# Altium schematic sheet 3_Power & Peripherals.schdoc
size 309 x 223 mm; Symbol: Artery_A4; Device: Artery_A4; Company: Artery Technology; Drawed: SD; Version: 1.0; Page Size: A4; @Project Name: AT-START-F456; @Page Count: 4; @Update Date: 2025-01-22; @Create Date: 2024-11-08; @Schematic Name: AT-START-F456 V1.0; @Page No: 3; @Page Name: Power & Peripherals; @Board Name: AT-START-F456_V1.0; @Create Time: 17:57:27; @Update Time: 17:53:06
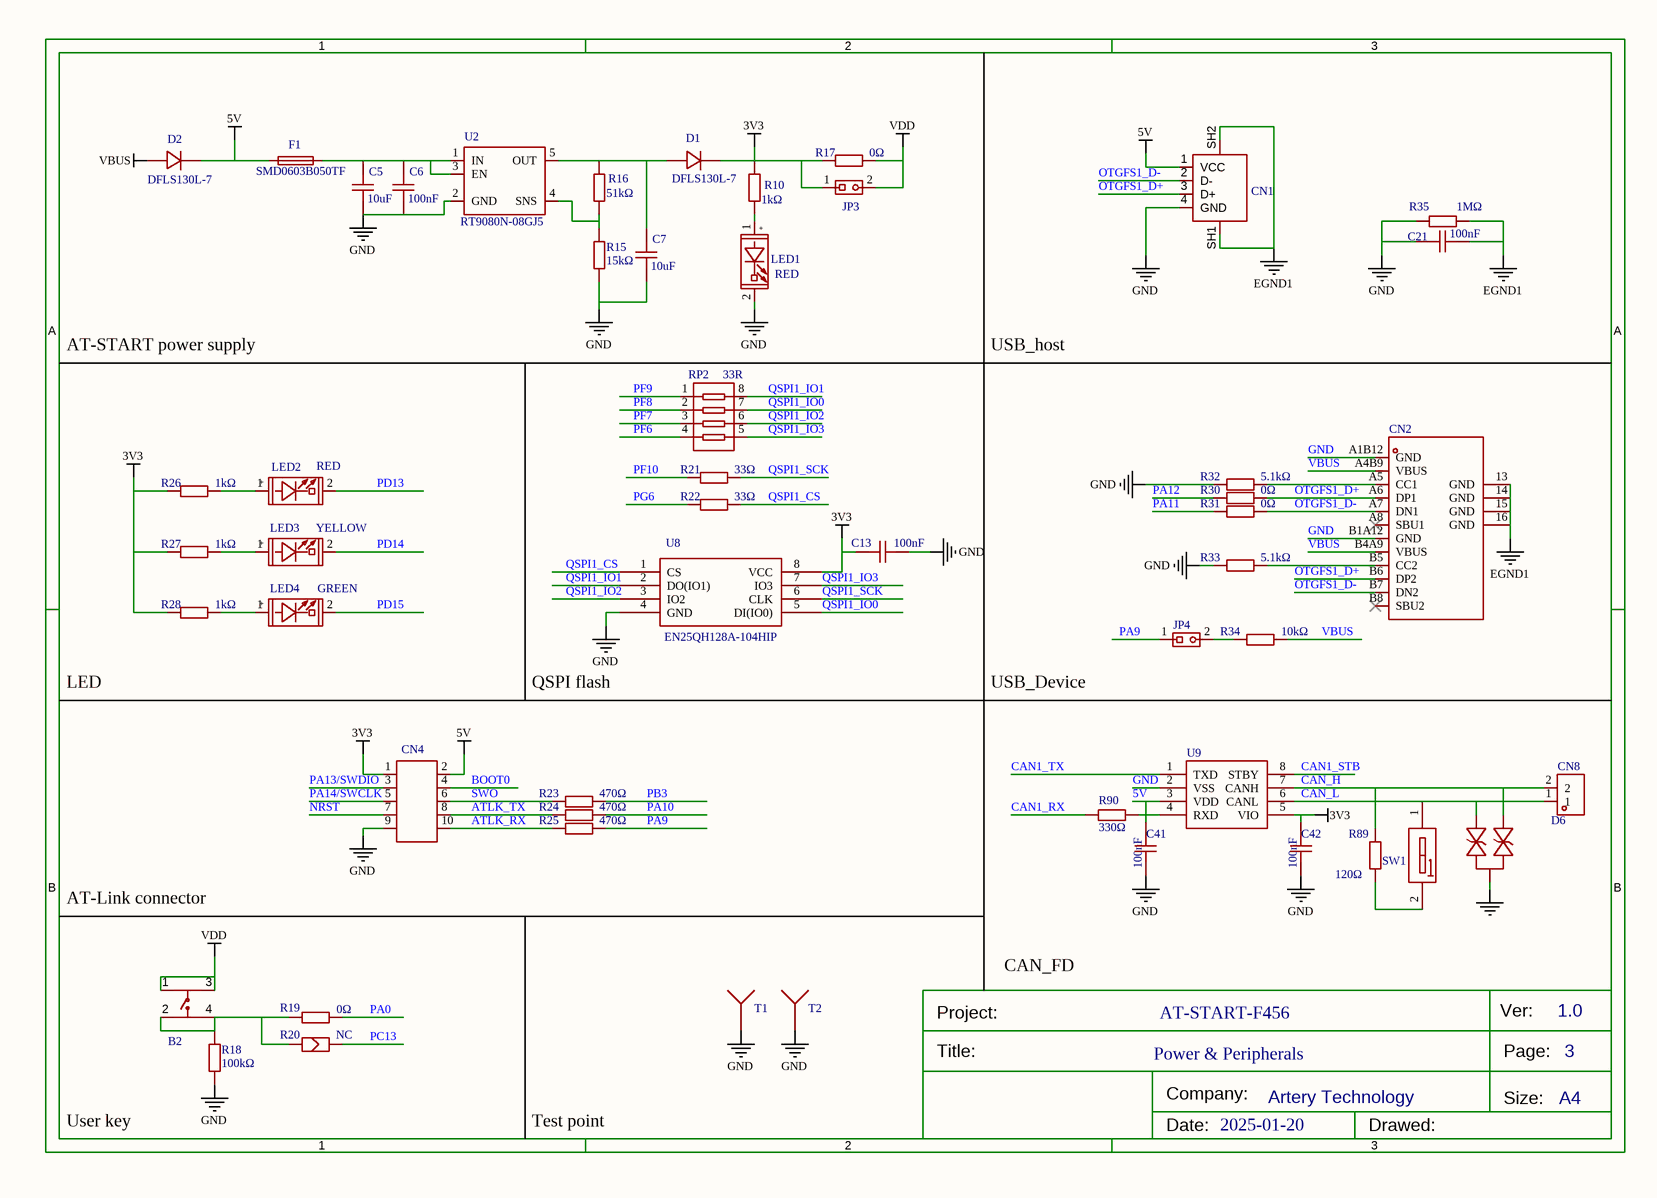
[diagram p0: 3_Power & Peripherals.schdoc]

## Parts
B2  贴片按键6*6*5 红色  [SW-SMD_4P-L6.0-W6.0-P4.50-LS9.0]  (value not drawn)
C5  10uF  [C0603]
C6  100nF  [C0603]
C7  10uF  [C0603]
C13  100nF  [C0603]
C21  100nF  [C0603]
C41  100nF  [C0603]
C42  100nF  [C0603]
CN1  JTJ-USB-AF-08  [USB-A-TH__USB-AF-90]  (value not drawn)
CN2  (no value)  [USB-C-SMD_TYPEC-304-BCP16]
CN4  CON10A_0  [HDR2X5]  (value not drawn)
CN8  KF301-5.0-2P  [CONN-TH_P5.00_KF301-5.0-2P]  (value not drawn)
D1  DFLS130L-7  [POWERDI-123_L2.8-W1.8-LS3.7-RD]
D2  DFLS130L-7  [POWERDI-123_L2.8-W1.8-LS3.7-RD]
D6  PESD2CANFD24V-TR  [SOT-23-3_L2.9-W1.3-P1.90-LS2.4-BR]  (value not drawn)
F1  SMD0603B050TF  [R0603]
JP3  Jumper 1x2P  [HEADER 1X2]  (value not drawn)
JP4  Jumper 1x2P  [HEADER 1X2]  (value not drawn)
LED1  RED  [LED0603]
LED2  RED  [LED0603]
LED3  YELLOW  [LED0603]
LED4  GREEN  [LED0603]
R10  1kΩ  [R0603]
R15  15kΩ  [R0603]
R16  51kΩ  [R0603]
R17  0Ω  [R0603]
R18  100kΩ  [R0603]
R19  0Ω  [R0603]
R20  NC  [SB-PAD]
R21  33Ω  [R0603]
R22  33Ω  [R0603]
R23  470Ω  [R0603]
R24  470Ω  [R0603]
R25  470Ω  [R0603]
R26  1kΩ  [R0603]
R27  1kΩ  [R0603]
R28  1kΩ  [R0603]
R30  0Ω  [R0603]
R31  0Ω  [R0603]
R32  value 5.1kΩ  [R0603]
R33  value 5.1kΩ  [R0603]
R34  10kΩ  [R0603]
R35  value 1MΩ  [R0603]
R89  120Ω  [R0603]
R90  330Ω  [R0603]
RP2  33R  [0603*4,8P4R]
SW1  DSWB01LHGET  [SW-TH_DSWB01LHGET]  (value not drawn)
T1  TESTPOINT TP-5006  [TESTHOOK]  (value not drawn)
T2  TESTPOINT TP-5006  [TESTHOOK]  (value not drawn)
U2  RT9080N-08GJ5  [SOT-23-5]
U8  EN25QH128A-104HIP  [SOIC-8_208MIL]
U9  MCP2562FD-E/SN  [SOIC-8_L4.9-W3.9-P1.27-LS6.0-BL]  (value not drawn)

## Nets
3V3: C13.1 C42.2 CN4.1 D1.1 JP3.1 R10.1 R17.1 R26.1 R27.1 R28.1 U8.8(VCC) U9.5(VIO)
5V: C41.2 CN1.1(VCC) CN4.2 D2.1 F1.1 U9.3(VDD)
EGND1: C21.1 CN1.SH1 CN1.SH2 CN2.13(GND) CN2.14(GND) CN2.15(GND) CN2.16(GND) R35.2
GND: C5.2 C6.2 C7.2 C13.2 C21.2 C41.1 C42.1 CN1.4(GND) CN2.A1B12(GND) CN2.B1A12(GND) CN4.9 D6.3 LED1.2(CATHODE) R15.2 R18.1 R32.1 R33.1 R35.1 T1.1 T2.1 U2.2(GND) U8.4(GND) U9.2(VSS)
VBUS: CN2.A4B9(VBUS) CN2.B4A9(VBUS) D2.2 R34.2
VDD: B2.1 B2.3 JP3.2 R17.2
ATLK_RX: CN4.10 R25.1
ATLK_TX: CN4.8 R24.1
BOOT0: CN4.4
CAN1_RX: R90.1
CAN1_STB: U9.8(STBY)
CAN1_TX: U9.1(TXD)
CAN_H: CN8.2 D6.1 R89.2 U9.7(CANH)
CAN_L: CN8.1 D6.2 SW1.1(A1) U9.6(CANL)
NRST: CN4.7
OTGFS1_D+: CN1.3(D+) CN2.A6(DP1) CN2.B6(DP2) R30.2
OTGFS1_D-: CN1.2(D-) CN2.A7(DN1) CN2.B7(DN2) R31.2
PA0: R19.2
PA9: JP4.1 R25.2
PA10: R24.2
PA11: R31.1
PA12: R30.1
PA13/SWDIO: CN4.3
PA14/SWCLK: CN4.5
PB3: R23.2
PC13: R20.2
PD13: LED2.2(CATHODE)
PD14: LED3.2(CATHODE)
PD15: LED4.2(CATHODE)
PF6: RP2.4
PF7: RP2.3
PF8: RP2.2
PF9: RP2.1
PF10: R21.1
PG6: R22.1
QSPI1_CS: R22.2 U8.1(CS)
QSPI1_IO0: RP2.7 U8.5(DI(IO0))
QSPI1_IO1: RP2.8 U8.2(DO(IO1))
QSPI1_IO2: RP2.6 U8.3(IO2)
QSPI1_IO3: RP2.5 U8.7(IO3)
QSPI1_SCK: R21.2 U8.6(CLK)
SWO: CN4.6 R23.1
NetB2_2: B2.2 B2.4 R18.2 R19.1 R20.1
NetC5_1: C5.1 C6.1 F1.2 U2.1(IN) U2.3(EN)
NetC7_1: C7.1 D1.2 R16.2 U2.5(OUT)
NetCN2_A5: CN2.A5(CC1) R32.2
NetCN2_B5: CN2.B5(CC2) R33.2
NetJP4_2: JP4.2 R34.1
NetLED1_1: LED1.1(ANODE) R10.2
NetLED2_1: LED2.1(ANODE) R26.2
NetLED3_1: LED3.1(ANODE) R27.2
NetLED4_1: LED4.1(ANODE) R28.2
NetR15_1: R15.1 R16.1 U2.4(SNS)
NetR89_1: R89.1 SW1.2
NetR90_2: R90.2 U9.4(RXD)

Not connected (* = marked no-connect by the designer): CN2 A8(SBU1)* B8(SBU2)*

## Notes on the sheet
- AT-START power supply
- USB_host
- LED
- QSPI flash
- USB_Device
- AT-Link connector
- CAN_FD
- AT-START-F456
- User key
- Test point
- 2025-01-20

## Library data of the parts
B2 = K2-1102SP-C3SC-04: Manufacturer: Korean Hroparts Elec; Symbol: 贴片按键6*6*5 黑色; Paste Type: expand; Convert to PCB: yes
C5 C7 = CL10A106KP8NNNC: Manufacturer: SAMSUNG(三星); Add into BOM: yes; Tolerance: ±10%; Voltage Rated: 10V; Temperature Coefficient: X5R; Origin Footprint: 0603_C-M
C6 C13 = CC0603KRX7R9BB104: Manufacturer: YAGEO(国巨); Add into BOM: yes; Tolerance: ±10%; Voltage Rated: 50V; Temperature Coefficient: X7R; Origin Footprint: 0603_C-M
C21 C41 C42 = CC0603KRX7R9BB104: Manufacturer: YAGEO(国巨); Add into BOM: yes; Tolerance: ±10%; Voltage Rated: 50V; Temperature Coefficient: X7R
CN1 = JTJ-USB-AF-08: Paste Type: expand; Convert to PCB: yes
CN2 = TYPEC-304-BCP16: Manufacturer: XUNPU(讯普); Add into BOM: yes; Connector Type: Type-C; Gender: 母座; Number of Contacts: 16.0; Number of Ports: 1; Mounting Sytle: 卧贴; Current Rating - Power (Max): 3A; Welding Temperature (Max): 260
CN4 = CON10A_0: Convert to PCB: yes
CN8 = KF301-5.0-2P: Manufacturer: KEFA(科发); Add into BOM: yes; Structure: 1x2P; Pitch: 5mm; Current Rating (Max): 17A; Voltage Rating (Max): 250V; Wire Gauge - AWG: 14~22; Wire Gauge - mm2: 1.5; Number of PINs Per Row: 2
D1 D2 = DFLS130L-7: Manufacturer: Diodes Incorporated; Paste Type: expand; Convert to PCB: yes
D6 = PESD2CANFD24V-TR: Manufacturer: Nexperia(安世); Add into BOM: yes; Reverse Stand-Off Voltage (Vrwm): 24V; Maximum Clamping Voltage: 42V; Breakdown Voltage: 25.5V; Type: ESD
F1 = SMD0603B035TF: Manufacturer: Brightking Elec (TAIWAN); Paste Type: expand; Convert to PCB: yes
JP3 JP4 = Jumper 1x2P: Convert to PCB: yes
LED1 LED2 = RED: Convert to PCB: yes
LED3 = YELLOW: Convert to PCB: yes
LED4 = GREEN: Convert to PCB: yes
R10 R26-R28 = 0603WAF1001T5E: Manufacturer: UNI-ROYAL(厚声); Add into BOM: yes; Tolerance: ±1%; Power(Watts): 100mW; Temperature Coefficient: ±100ppm/℃; Overload Voltage (Max): 75V
R15 = 0603WAF1502T5E: Manufacturer: UNI-ROYAL(厚声); Add into BOM: yes; Tolerance: ±1%; Power(Watts): 100mW; Temperature Coefficient: ±100ppm/℃; Overload Voltage (Max): 75V
R16 = 0603WAF5102T5E: Manufacturer: UNI-ROYAL(厚声); Add into BOM: yes; Tolerance: ±1%; Power(Watts): 100mW; Temperature Coefficient: ±100ppm/℃; Overload Voltage (Max): 75V
R17 R19 = 0603WAF0000T5E: Manufacturer: UNI-ROYAL(厚声); Add into BOM: yes; Tolerance: ±1%; Power(Watts): 100mW; Overload Voltage (Max): 75V
R18 = 0603WAF1003T5E: Manufacturer: UNI-ROYAL(厚声); Add into BOM: yes; Tolerance: ±1%; Power(Watts): 100mW; Temperature Coefficient: ±100ppm/℃; Overload Voltage (Max): 75V
R20 = NC: Convert to PCB: yes
R21 R22 = 0603WAF330JT5E: Manufacturer: UNI-ROYAL(厚声); Add into BOM: yes; Tolerance: ±1%; Power(Watts): 100mW; Temperature Coefficient: ±100ppm/℃; Overload Voltage (Max): 75V
R23-R25 = 0603WAF4700T5E: Manufacturer: UNI-ROYAL(厚声); Add into BOM: yes; Tolerance: ±1%; Power(Watts): 100mW; Temperature Coefficient: ±100ppm/℃; Overload Voltage (Max): 75V
R30 R31 = 0603WAF0000T5E: Manufacturer: UNI-ROYAL(厚声); Add into BOM: yes; Tolerance: ±1%; Power(Watts): 100mW; Overload Voltage (Max): 75V; Temperature Coefficient: ±100ppm/℃
R32 R33 = 0603WAF5101T5E: Manufacturer: UNI-ROYAL(厚声); Add into BOM: yes; Tolerance: ±1%; Power(Watts): 1/10W; Temperature Coefficient: ±100ppm/; Overload Voltage (Max): 75V
R34 = 0603WAF1002T5E: Manufacturer: UNI-ROYAL(厚声); Add into BOM: yes; Tolerance: ±1%; Power(Watts): 100mW; Temperature Coefficient: ±100ppm/℃; Overload Voltage (Max): 75V
R35 = RC0603FR-071ML: Manufacturer: YAGEO(国巨); Add into BOM: yes; Tolerance: ±1%; Power(Watts): 100mW; Temperature Coefficient: ±100ppm/; Overload Voltage (Max): 75V
R89 = 0603WAF1200T5E: Manufacturer: UNI-ROYAL(厚声); Add into BOM: yes; Tolerance: ±1%; Power(Watts): 100mW; Overload Voltage (Max): 75V; Temperature Coefficient: ±100ppm/℃
R90 = 0603WAF3300T5E: Manufacturer: UNI-ROYAL(厚声); Add into BOM: yes; Tolerance: ±1%; Power(Watts): 100mW; Overload Voltage (Max): 75V; Temperature Coefficient: ±100ppm/℃
RP2 = 33R: Convert to PCB: yes
SW1 = DSWB01LHGET: Manufacturer: YE; Add into BOM: yes; Circuit: 单刀单掷; Number of Positions: 1位
T1 T2 = TESTPOINT TP-5006: Convert to PCB: yes
U2 = RT9080N-08GJ5: Convert to PCB: yes
U8 = EN25QH128A-104HIP: Convert to PCB: yes
U9 = MCP2562FD-E/SN: Manufacturer: MICROCHIP(美国微芯); Add into BOM: yes; Data Rate: 8Mbps; Supply Voltage: 4.5V~5.5V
